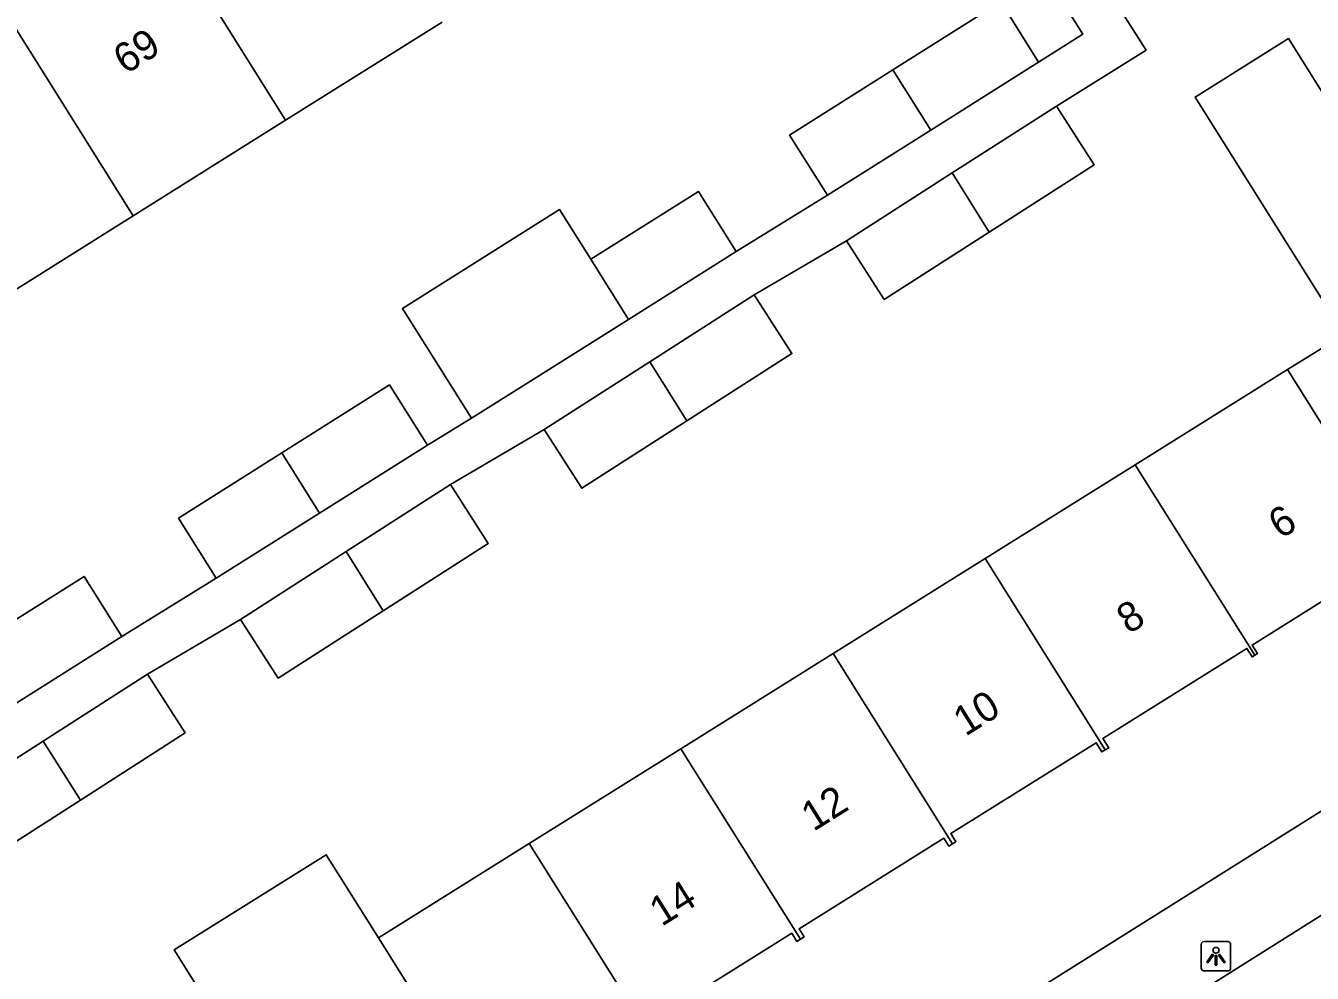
# Model space of a CAD drawing. Extents: x 160077 to 160945, y 386481 to 387498.
# Drawn here: x 160283.4 to 160327.02, y 387111.2 to 387143.33 of the extents above; entities that cross this region are included whole.
import ezdxf

# ---------------------------------------------------------------- set-up
doc = ezdxf.new("R2010")
doc.units = 0
for name, color, linetype in [('IMGEO_Lichtpunt', 7, 'Continuous'), ('IMGEO_Pand', 7, 'Continuous'), ('IMGEO_Pand_nummerreeks', 7, 'Continuous'), ('IMGEO_Rijbaan_lokaal_open', 7, 'Continuous'), ('IMGEO_Voetpad_open', 7, 'Continuous')]:
    doc.layers.add(name, color=color, linetype=linetype)

msp = doc.modelspace()

# ---------------------------------------------------------------- linework, layer by layer
at = {"layer": 'IMGEO_Lichtpunt'}
for p, q in [((160323.256, 387112.177), (160323.256, 387111.37)), ((160323.256, 387112.177), (160323.256, 387111.37)), ((160324.158, 387112.272), (160323.35, 387112.272)), ((160324.158, 387112.272), (160323.35, 387112.272)), ((160324.252, 387111.37), (160324.252, 387112.177)), ((160324.252, 387111.37), (160324.252, 387112.177)), ((160323.35, 387111.276), (160324.158, 387111.276)), ((160323.35, 387111.276), (160324.158, 387111.276))]:
    msp.add_line(p, q, dxfattribs=at)
for points in [[(160323.63, 387111.841), (160323.669, 387111.813), (160323.481, 387111.551), (160323.443, 387111.578), (160323.63, 387111.841)], [(160323.732, 387111.793), (160323.779, 387111.793), (160323.779, 387111.471), (160323.732, 387111.471), (160323.732, 387111.793)], [(160323.842, 387111.813), (160323.88, 387111.84), (160324.067, 387111.578), (160324.028, 387111.55), (160323.842, 387111.813)]]:
    msp.add_lwpolyline(points, dxfattribs=at)
msp.add_circle((160323.755, 387111.975), 0.0994, dxfattribs=at)
for centre, start, end in [((160323.35, 387112.177), 90, 180), ((160323.35, 387112.177), 90, 180), ((160324.158, 387112.177), 0, 90), ((160324.158, 387112.177), 0, 90), ((160323.35, 387111.37), 180, 270), ((160323.35, 387111.37), 180, 270), ((160324.158, 387111.37), 270, 0), ((160324.158, 387111.37), 270, 360)]:
    msp.add_arc(centre, 0.0946, start, end, dxfattribs=at)
at = {"layer": 'IMGEO_Pand'}
for points in [[(160288.249, 387146.446), (160292.212, 387140.123)], [(160312.804, 387141.83), (160316.456, 387144.133), (160317.74, 387142.096)], [(160283.079, 387143.205), (160287.042, 387136.883)], [(160297.518, 387143.449), (160292.212, 387140.123)], [(160331.264, 387134.838), (160326.213, 387142.89), (160323.049, 387140.905), (160328.097, 387132.859), (160326.185, 387131.665)], [(160310.583, 387137.583), (160309.299, 387139.62), (160312.804, 387141.83)], [(160312.804, 387141.83), (160314.083, 387139.79)], [(160317.74, 387142.096), (160314.083, 387139.79)], [(160314.811, 387138.333), (160318.35, 387140.604)], [(160318.35, 387140.604), (160319.627, 387138.612), (160316.068, 387136.329)], [(160292.212, 387140.123), (160287.042, 387136.883)], [(160314.083, 387139.79), (160310.583, 387137.583)], [(160311.229, 387136.035), (160314.811, 387138.333)], [(160314.811, 387138.333), (160316.068, 387136.329)], [(160302.558, 387135.409), (160306.209, 387137.711), (160307.493, 387135.674)], [(160302.558, 387135.409), (160301.501, 387137.095), (160296.174, 387133.735), (160298.519, 387130.015)], [(160287.042, 387136.883), (160282.011, 387133.73)], [(160316.068, 387136.329), (160312.506, 387134.044), (160311.229, 387136.035)], [(160303.837, 387133.369), (160302.558, 387135.409)], [(160307.493, 387135.674), (160303.837, 387133.369)], [(160304.562, 387131.93), (160308.102, 387134.201)], [(160308.102, 387134.201), (160309.379, 387132.209), (160305.819, 387129.926)], [(160303.837, 387133.369), (160300.336, 387131.161), (160298.519, 387130.015)], [(160300.981, 387129.632), (160304.562, 387131.93)], [(160304.562, 387131.93), (160305.819, 387129.926)], [(160326.185, 387131.665), (160321.019, 387128.437)], [(160326.185, 387131.665), (160330.236, 387125.207)], [(160292.082, 387128.843), (160295.733, 387131.145), (160297.017, 387129.108)], [(160305.819, 387129.926), (160302.258, 387127.641), (160300.981, 387129.632)], [(160289.86, 387124.595), (160288.576, 387126.632), (160292.082, 387128.843)], [(160292.082, 387128.843), (160293.361, 387126.803)], [(160297.017, 387129.108), (160293.361, 387126.803)], [(160321.019, 387128.437), (160315.933, 387125.259)], [(160325.069, 387121.981), (160321.019, 387128.437)], [(160294.265, 387125.495), (160297.804, 387127.766)], [(160297.804, 387127.766), (160299.081, 387125.774), (160295.522, 387123.491)], [(160293.361, 387126.803), (160289.86, 387124.595)], [(160290.683, 387123.197), (160294.265, 387125.495)], [(160294.265, 387125.495), (160295.522, 387123.491)], [(160315.933, 387125.259), (160310.771, 387122.034)], [(160315.933, 387125.259), (160320.002, 387118.772)], [(160325.069, 387121.981), (160325.159, 387122.037), (160324.98, 387122.323), (160329.952, 387125.436), (160330.134, 387125.144), (160330.236, 387125.207)], [(160281.726, 387122.352), (160285.377, 387124.654), (160286.661, 387122.617)], [(160295.522, 387123.491), (160291.96, 387121.206), (160290.683, 387123.197)], [(160286.661, 387122.617), (160283.005, 387120.312)], [(160320.002, 387118.772), (160320.117, 387118.843), (160319.922, 387119.157), (160324.803, 387122.213), (160324.982, 387121.926), (160325.069, 387121.981)], [(160310.771, 387122.034), (160305.616, 387118.812)], [(160314.82, 387115.581), (160310.771, 387122.034)], [(160283.995, 387119.071), (160287.534, 387121.342)], [(160287.534, 387121.342), (160288.811, 387119.35), (160285.252, 387117.067)], [(160280.413, 387116.773), (160283.995, 387119.071)], [(160283.995, 387119.071), (160285.252, 387117.067)], [(160305.616, 387118.812), (160300.473, 387115.599)], [(160305.616, 387118.812), (160309.667, 387112.353)], [(160314.82, 387115.581), (160314.939, 387115.655), (160314.767, 387115.93), (160319.695, 387119.015), (160319.89, 387118.702), (160320.002, 387118.772)], [(160285.252, 387117.067), (160281.69, 387114.782), (160280.413, 387116.773)], [(160309.667, 387112.353), (160309.79, 387112.43), (160309.618, 387112.706), (160314.527, 387115.779), (160314.698, 387115.505), (160314.82, 387115.581)], [(160295.356, 387112.402), (160293.59, 387115.217), (160288.434, 387111.995), (160290.2, 387109.18)], [(160300.473, 387115.599), (160295.356, 387112.402)], [(160304.535, 387109.124), (160300.473, 387115.599)], [(160299.435, 387105.901), (160295.356, 387112.402)], [(160304.535, 387109.124), (160304.632, 387109.185), (160304.452, 387109.472), (160309.372, 387112.552), (160309.545, 387112.276), (160309.667, 387112.353)]]:
    msp.add_lwpolyline(points, dxfattribs=at)
at = {"layer": 'IMGEO_Rijbaan_lokaal_open'}
msp.add_lwpolyline([(160312.287, 387103.692), (160327.734, 387113.414), (160349.554, 387127.092), (160358.054, 387132.381)], dxfattribs=at)
at = {"layer": 'IMGEO_Voetpad_open'}
for points in [[(160312.905, 387153.093), (160319.242, 387143.043), (160317.74, 387142.096)], [(160316.293, 387151.523), (160315.822, 387151.223), (160321.391, 387142.502), (160318.35, 387140.604)], [(160310.583, 387137.583), (160307.493, 387135.674)], [(160311.229, 387136.035), (160308.102, 387134.201)], [(160298.519, 387130.015), (160297.017, 387129.108)], [(160300.981, 387129.632), (160297.804, 387127.766)], [(160268.541, 387109.335), (160267.725, 387108.811), (160280.982, 387087.594), (160343.569, 387126.901)], [(160289.86, 387124.595), (160286.661, 387122.617)], [(160290.683, 387123.197), (160287.534, 387121.342)]]:
    msp.add_lwpolyline(points, dxfattribs=at)

# ---------------------------------------------------------------- texts
at = {"layer": 'IMGEO_Pand_nummerreeks'}
for s, rotation, p in [('69', 32.0777, (160286.784, 387141.657)), ('6', 32.0455, (160325.944, 387125.9)), ('8', 32.0455, (160320.799, 387122.679)), ('10', 32.0455, (160315.26, 387119.212)), ('12', 32.0455, (160310.106, 387115.985)), ('14', 32.0455, (160304.96, 387112.763))]:
    msp.add_text(s, height=1, rotation=rotation, dxfattribs=at).set_placement(p)

doc.saveas('drawing.dxf')
